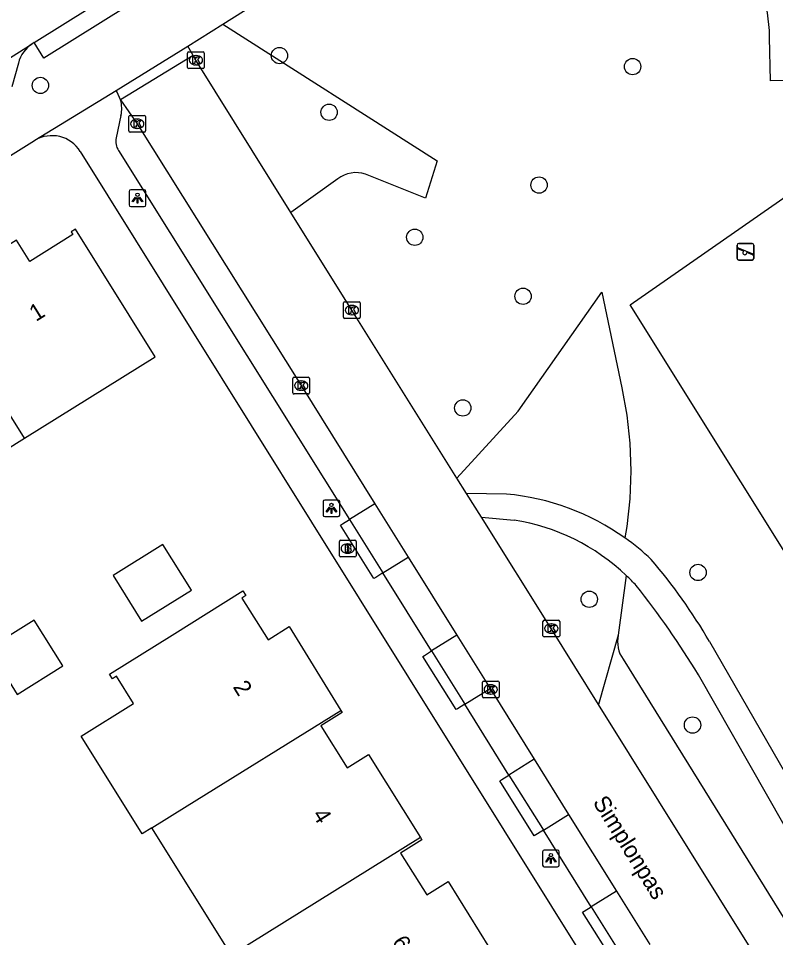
# Model space of a CAD drawing. Extents: x 158838 to 160074, y 386376 to 387776.
# Drawn here: x 159109.8 to 159155.2, y 387026.3 to 387081.4 of the extents above; entities that cross this region are included whole.
import ezdxf

# ---------------------------------------------------------------- set-up
doc = ezdxf.new("R2010")
doc.units = 0
for name, color, linetype in [('IMGEO_Boom', 7, 'Continuous'), ('IMGEO_Brandkraan', 7, 'Continuous'), ('IMGEO_Groenvoorziening', 7, 'Continuous'), ('IMGEO_Kolk', 7, 'Continuous'), ('IMGEO_Lichtpunt', 7, 'Continuous'), ('IMGEO_Muur', 7, 'Continuous'), ('IMGEO_Openbare_ruimte_label', 7, 'Continuous'), ('IMGEO_Pand', 7, 'Continuous'), ('IMGEO_Pand_nummerreeks', 7, 'Continuous'), ('IMGEO_Rijbaan_lokaal_open', 7, 'Continuous'), ('IMGEO_Speelvoorziening', 7, 'Continuous'), ('IMGEO_Voetpad_halfverhard', 7, 'Continuous'), ('IMGEO_Voetpad_open', 7, 'Continuous')]:
    doc.layers.add(name, color=color, linetype=linetype)

msp = doc.modelspace()

# ---------------------------------------------------------------- linework, layer by layer
at = {"layer": 'IMGEO_Boom'}
for centre in [(159125.412, 387079.149), (159146.581, 387078.488), (159111.083, 387077.358), (159128.389, 387075.753), (159140.974, 387071.393), (159133.524, 387068.262), (159140.012, 387064.726), (159136.402, 387058.036), (159150.502, 387048.181), (159143.982, 387046.575), (159150.172, 387039.039)]:
    msp.add_circle(centre, 0.489, dxfattribs=at)
at = {"layer": 'IMGEO_Brandkraan'}
for p, q in [((159129.004, 387049.186), (159129.004, 387050.038)), ((159129.079, 387050.112), (159129.931, 387050.112)), ((159129.492, 387049.892), (159129.517, 387049.892)), ((159130.005, 387050.038), (159130.005, 387049.186)), ((159129.515, 387049.332), (159129.49, 387049.332)), ((159129.931, 387049.112), (159129.079, 387049.112))]:
    msp.add_line(p, q, dxfattribs=at)
for points in [[(159129.004, 387049.186), (159129.004, 387050.038)], [(159129.079, 387050.112), (159129.931, 387050.112)], [(159130.005, 387050.038), (159130.005, 387049.186)], [(159129.352, 387049.812), (159129.352, 387049.412), (159129.565, 387049.412)], [(159129.583, 387049.812), (159129.352, 387049.812)], [(159129.531, 387049.731), (159129.477, 387049.731), (159129.477, 387049.655)], [(159129.477, 387049.655), (159129.53, 387049.655)], [(159129.539, 387049.579), (159129.477, 387049.579), (159129.477, 387049.498)], [(159129.477, 387049.498), (159129.539, 387049.498)], [(159129.931, 387049.112), (159129.079, 387049.112)]]:
    msp.add_lwpolyline(points, dxfattribs=at)
for centre, radius, start, end in [((159129.081, 387050.036), 0.0765, 91.552, 178.448), ((159129.081, 387050.036), 0.0765, 91.552, 178.448), ((159129.929, 387050.036), 0.0765, 1.552, 88.448), ((159129.929, 387050.036), 0.0765, 1.552, 88.448), ((159129.532, 387049.693), 0.0379, 267.8285, 90.9355), ((159129.54, 387049.538), 0.0404, 269.8759, 90.5077), ((159129.571, 387049.663), 0.251, 268.6676, 293.5347), ((159129.587, 387049.667), 0.145, 59.4692, 91.5367), ((159129.612, 387049.714), 0.0922, 285.5137, 58.1501), ((159129.617, 387049.522), 0.105, 301.3115, 78.989), ((159129.081, 387049.188), 0.0765, 181.552, 268.448), ((159129.081, 387049.188), 0.0765, 181.552, 268.448), ((159129.929, 387049.188), 0.0765, 271.552, 358.448), ((159129.929, 387049.188), 0.0765, 271.552, 358.448)]:
    msp.add_arc(centre, radius, start, end, dxfattribs=at)
for centre, major_axis, ratio, start_param, end_param in [((159129.491, 387049.612), (-0.387, 0.002), 0.722429, 4.712389, 7.853982), ((159129.516, 387049.612), (-0.39, 0.002), 0.717154, 1.570796, 4.712389)]:
    msp.add_ellipse(centre, major_axis=major_axis, ratio=ratio, start_param=start_param, end_param=end_param, dxfattribs=at)
at = {"layer": 'IMGEO_Groenvoorziening'}
for points in [[(159156.656, 387089.592), (159156.492, 387077.665), (159154.841, 387077.644), (159154.788, 387080.232), (159154.777, 387080.645), (159154.665, 387081.712), (159154.435, 387082.76), (159154.09, 387083.777), (159153.633, 387084.748), (159153.071, 387085.662), (159152.41, 387086.508), (159141.336, 387093.187)], [(159122.014, 387081.038), (159134.861, 387072.838), (159134.173, 387070.612), (159130.575, 387072.05)], [(159158.739, 387072.783), (159178.64, 387040.984), (159166.329, 387032.414), (159146.428, 387064.213), (159158.739, 387072.783)], [(159128.911, 387071.76), (159126.097, 387069.747)], [(159136.054, 387053.836), (159139.723, 387057.851), (159144.742, 387064.973), (159145.94, 387059.243), (159146.237, 387057.598), (159146.415, 387055.935), (159146.474, 387054.265), (159146.412, 387052.594), (159146.231, 387050.932), (159146.122, 387050.251)], [(159146.204, 387048.002), (159145.724, 387044.428)], [(159145.724, 387044.428), (159144.539, 387040.277)], [(159146.011, 387042.982), (159178.034, 386991.406)]]:
    msp.add_lwpolyline(points, dxfattribs=at)
for centre, radius, start, end in [((159130.019, 387070.32), 1.817, 72.1969, 127.5754), ((159147.494, 387044.028), 1.815, 167.2666, 215.1855)]:
    msp.add_arc(centre, radius, start, end, dxfattribs=at)
at = {"layer": 'IMGEO_Kolk'}
for p, q in [((159119.902, 387078.442), (159119.902, 387079.294)), ((159119.977, 387079.368), (159120.829, 387079.368)), ((159120.39, 387079.148), (159120.415, 387079.148)), ((159120.903, 387079.294), (159120.903, 387078.442)), ((159120.413, 387078.588), (159120.388, 387078.588)), ((159120.829, 387078.368), (159119.977, 387078.368)), ((159116.384, 387074.639), (159116.384, 387075.491)), ((159116.459, 387075.565), (159117.311, 387075.565)), ((159116.872, 387075.345), (159116.897, 387075.345)), ((159117.385, 387075.491), (159117.385, 387074.639)), ((159116.895, 387074.785), (159116.87, 387074.785)), ((159117.311, 387074.565), (159116.459, 387074.565)), ((159129.253, 387063.476), (159129.253, 387064.328)), ((159129.328, 387064.402), (159130.18, 387064.402)), ((159129.741, 387064.182), (159129.766, 387064.182)), ((159130.254, 387064.328), (159130.254, 387063.476)), ((159129.764, 387063.622), (159129.739, 387063.622)), ((159130.18, 387063.402), (159129.328, 387063.402)), ((159126.214, 387058.948), (159126.214, 387059.8)), ((159126.289, 387059.874), (159127.141, 387059.874)), ((159127.215, 387059.8), (159127.215, 387058.948)), ((159126.702, 387059.654), (159126.727, 387059.654)), ((159127.141, 387058.874), (159126.289, 387058.874)), ((159126.725, 387059.094), (159126.7, 387059.094)), ((159141.208, 387044.392), (159141.208, 387045.244)), ((159141.283, 387045.318), (159142.135, 387045.318)), ((159141.696, 387045.098), (159141.721, 387045.098)), ((159142.209, 387045.244), (159142.209, 387044.392)), ((159142.135, 387044.318), (159141.283, 387044.318)), ((159141.719, 387044.538), (159141.694, 387044.538)), ((159137.576, 387040.752), (159137.576, 387041.604)), ((159137.651, 387041.678), (159138.503, 387041.678)), ((159138.577, 387041.604), (159138.577, 387040.752)), ((159138.064, 387041.458), (159138.089, 387041.458)), ((159138.503, 387040.678), (159137.651, 387040.678)), ((159138.087, 387040.898), (159138.062, 387040.898))]:
    msp.add_line(p, q, dxfattribs=at)
for points in [[(159119.902, 387078.442), (159119.902, 387079.294)], [(159119.977, 387079.368), (159120.829, 387079.368)], [(159120.223, 387079.068), (159120.346, 387079.068), (159120.346, 387078.917), (159120.476, 387079.068), (159120.64, 387079.068), (159120.494, 387078.917), (159120.647, 387078.668), (159120.495, 387078.668), (159120.41, 387078.832), (159120.346, 387078.765), (159120.346, 387078.668), (159120.223, 387078.668), (159120.223, 387079.068)], [(159120.903, 387079.294), (159120.903, 387078.442)], [(159120.829, 387078.368), (159119.977, 387078.368)], [(159116.384, 387074.639), (159116.384, 387075.491)], [(159116.459, 387075.565), (159117.311, 387075.565)], [(159116.705, 387075.265), (159116.828, 387075.265), (159116.828, 387075.114), (159116.958, 387075.265), (159117.122, 387075.265), (159116.976, 387075.114), (159117.129, 387074.865), (159116.977, 387074.865), (159116.892, 387075.029), (159116.828, 387074.962), (159116.828, 387074.865), (159116.705, 387074.865), (159116.705, 387075.265)], [(159117.385, 387075.491), (159117.385, 387074.639)], [(159117.311, 387074.565), (159116.459, 387074.565)], [(159129.253, 387063.476), (159129.253, 387064.328)], [(159129.328, 387064.402), (159130.18, 387064.402)], [(159130.254, 387064.328), (159130.254, 387063.476)], [(159129.574, 387064.102), (159129.697, 387064.102), (159129.697, 387063.951), (159129.827, 387064.102), (159129.991, 387064.102), (159129.845, 387063.951), (159129.998, 387063.702), (159129.846, 387063.702), (159129.761, 387063.866), (159129.697, 387063.799), (159129.697, 387063.702), (159129.574, 387063.702), (159129.574, 387064.102)], [(159130.18, 387063.402), (159129.328, 387063.402)], [(159126.214, 387058.948), (159126.214, 387059.8)], [(159126.289, 387059.874), (159127.141, 387059.874)], [(159127.215, 387059.8), (159127.215, 387058.948)], [(159126.535, 387059.574), (159126.658, 387059.574), (159126.658, 387059.423), (159126.788, 387059.574), (159126.952, 387059.574), (159126.806, 387059.423), (159126.959, 387059.174), (159126.807, 387059.174), (159126.722, 387059.338), (159126.658, 387059.271), (159126.658, 387059.174), (159126.535, 387059.174), (159126.535, 387059.574)], [(159127.141, 387058.874), (159126.289, 387058.874)], [(159141.208, 387044.392), (159141.208, 387045.244)], [(159141.283, 387045.318), (159142.135, 387045.318)], [(159141.529, 387045.018), (159141.652, 387045.018), (159141.652, 387044.867), (159141.782, 387045.018), (159141.946, 387045.018), (159141.8, 387044.867), (159141.953, 387044.618), (159141.801, 387044.618), (159141.716, 387044.782), (159141.652, 387044.715), (159141.652, 387044.618), (159141.529, 387044.618), (159141.529, 387045.018)], [(159142.209, 387045.244), (159142.209, 387044.392)], [(159142.135, 387044.318), (159141.283, 387044.318)], [(159137.576, 387040.752), (159137.576, 387041.604)], [(159137.651, 387041.678), (159138.503, 387041.678)], [(159138.577, 387041.604), (159138.577, 387040.752)], [(159137.897, 387041.378), (159138.02, 387041.378), (159138.02, 387041.227), (159138.15, 387041.378), (159138.314, 387041.378), (159138.168, 387041.227), (159138.321, 387040.978), (159138.169, 387040.978), (159138.084, 387041.142), (159138.02, 387041.075), (159138.02, 387040.978), (159137.897, 387040.978), (159137.897, 387041.378)], [(159138.503, 387040.678), (159137.651, 387040.678)]]:
    msp.add_lwpolyline(points, dxfattribs=at)
for centre, start, end in [((159119.979, 387079.292), 91.552, 178.448), ((159119.979, 387079.292), 91.552, 178.448), ((159120.827, 387079.292), 1.552, 88.448), ((159120.827, 387079.292), 1.552, 88.448), ((159119.979, 387078.444), 181.552, 268.448), ((159119.979, 387078.444), 181.552, 268.448), ((159120.827, 387078.444), 271.552, 358.448), ((159120.827, 387078.444), 271.552, 358.448), ((159116.461, 387075.489), 91.552, 178.448), ((159116.461, 387075.489), 91.552, 178.448), ((159117.309, 387075.489), 1.552, 88.448), ((159117.309, 387075.489), 1.552, 88.448), ((159116.461, 387074.641), 181.552, 268.448), ((159116.461, 387074.641), 181.552, 268.448), ((159117.309, 387074.641), 271.552, 358.448), ((159117.309, 387074.641), 271.552, 358.448), ((159129.33, 387064.326), 91.552, 178.448), ((159129.33, 387064.326), 91.552, 178.448), ((159130.178, 387064.326), 1.552, 88.448), ((159130.178, 387064.326), 1.552, 88.448), ((159129.33, 387063.478), 181.552, 268.448), ((159129.33, 387063.478), 181.552, 268.448), ((159130.178, 387063.478), 271.552, 358.448), ((159130.178, 387063.478), 271.552, 358.448), ((159126.291, 387059.798), 91.552, 178.448), ((159126.291, 387059.798), 91.552, 178.448), ((159127.139, 387059.798), 1.552, 88.448), ((159127.139, 387059.798), 1.552, 88.448), ((159126.291, 387058.95), 181.552, 268.448), ((159126.291, 387058.95), 181.552, 268.448), ((159127.139, 387058.95), 271.552, 358.448), ((159127.139, 387058.95), 271.552, 358.448), ((159141.285, 387045.242), 91.552, 178.448), ((159141.285, 387045.242), 91.552, 178.448), ((159142.133, 387045.242), 1.552, 88.448), ((159142.133, 387045.242), 1.552, 88.448), ((159141.285, 387044.394), 181.552, 268.448), ((159141.285, 387044.394), 181.552, 268.448), ((159142.133, 387044.394), 271.552, 358.448), ((159142.133, 387044.394), 271.552, 358.448), ((159137.653, 387041.602), 91.552, 178.448), ((159137.653, 387041.602), 91.552, 178.448), ((159138.501, 387041.602), 1.552, 88.448), ((159138.501, 387041.602), 1.552, 88.448), ((159137.653, 387040.754), 181.552, 268.448), ((159137.653, 387040.754), 181.552, 268.448), ((159138.501, 387040.754), 271.552, 358.448), ((159138.501, 387040.754), 271.552, 358.448)]:
    msp.add_arc(centre, 0.0765, start, end, dxfattribs=at)
for centre, major_axis, ratio, start_param, end_param in [((159120.389, 387078.868), (-0.387, 0.002), 0.722429, 4.712389, 7.853982), ((159120.414, 387078.868), (-0.39, 0.002), 0.717154, 1.570796, 4.712389), ((159116.871, 387075.065), (-0.387, 0.002), 0.722429, 4.712389, 7.853982), ((159116.896, 387075.065), (-0.39, 0.002), 0.717154, 1.570796, 4.712389), ((159129.74, 387063.902), (-0.387, 0.002), 0.722429, 4.712389, 7.853982), ((159129.765, 387063.902), (-0.39, 0.002), 0.717154, 1.570796, 4.712389), ((159126.701, 387059.374), (-0.387, 0.002), 0.722429, 4.712389, 7.853982), ((159126.726, 387059.374), (-0.39, 0.002), 0.717154, 1.570796, 4.712389), ((159141.695, 387044.818), (-0.387, 0.002), 0.722429, 4.712389, 7.853982), ((159141.72, 387044.818), (-0.39, 0.002), 0.717154, 1.570796, 4.712389), ((159138.063, 387041.178), (-0.387, 0.002), 0.722429, 4.712389, 7.853982), ((159138.088, 387041.178), (-0.39, 0.002), 0.717154, 1.570796, 4.712389)]:
    msp.add_ellipse(centre, major_axis=major_axis, ratio=ratio, start_param=start_param, end_param=end_param, dxfattribs=at)
at = {"layer": 'IMGEO_Lichtpunt'}
for p, q in [((159116.403, 387071.01), (159116.403, 387070.203)), ((159116.403, 387071.01), (159116.403, 387070.203)), ((159117.305, 387071.105), (159116.497, 387071.105)), ((159117.305, 387071.105), (159116.497, 387071.105)), ((159117.399, 387070.203), (159117.399, 387071.01)), ((159117.399, 387070.203), (159117.399, 387071.01)), ((159116.497, 387070.109), (159117.305, 387070.109)), ((159116.497, 387070.109), (159117.305, 387070.109)), ((159128.03, 387052.428), (159128.03, 387051.621)), ((159128.03, 387052.428), (159128.03, 387051.621)), ((159128.932, 387052.523), (159128.124, 387052.523)), ((159128.932, 387052.523), (159128.124, 387052.523)), ((159129.026, 387051.621), (159129.026, 387052.428)), ((159129.026, 387051.621), (159129.026, 387052.428)), ((159128.124, 387051.527), (159128.932, 387051.527)), ((159128.124, 387051.527), (159128.932, 387051.527)), ((159141.183, 387031.454), (159141.183, 387030.647)), ((159141.183, 387031.454), (159141.183, 387030.647)), ((159142.085, 387031.549), (159141.277, 387031.549)), ((159142.085, 387031.549), (159141.277, 387031.549)), ((159142.179, 387030.647), (159142.179, 387031.454)), ((159142.179, 387030.647), (159142.179, 387031.454)), ((159141.277, 387030.553), (159142.085, 387030.553)), ((159141.277, 387030.553), (159142.085, 387030.553))]:
    msp.add_line(p, q, dxfattribs=at)
for points in [[(159116.777, 387070.674), (159116.816, 387070.646), (159116.628, 387070.384), (159116.59, 387070.411), (159116.777, 387070.674)], [(159116.879, 387070.626), (159116.926, 387070.626), (159116.926, 387070.304), (159116.879, 387070.304), (159116.879, 387070.626)], [(159116.989, 387070.646), (159117.027, 387070.673), (159117.214, 387070.411), (159117.175, 387070.383), (159116.989, 387070.646)], [(159128.404, 387052.092), (159128.443, 387052.064), (159128.255, 387051.802), (159128.217, 387051.829), (159128.404, 387052.092)], [(159128.506, 387052.044), (159128.553, 387052.044), (159128.553, 387051.722), (159128.506, 387051.722), (159128.506, 387052.044)], [(159128.616, 387052.064), (159128.654, 387052.091), (159128.841, 387051.829), (159128.802, 387051.801), (159128.616, 387052.064)], [(159141.557, 387031.118), (159141.596, 387031.09), (159141.408, 387030.828), (159141.37, 387030.855), (159141.557, 387031.118)], [(159141.769, 387031.09), (159141.807, 387031.117), (159141.994, 387030.855), (159141.955, 387030.827), (159141.769, 387031.09)], [(159141.659, 387031.07), (159141.706, 387031.07), (159141.706, 387030.748), (159141.659, 387030.748), (159141.659, 387031.07)]]:
    msp.add_lwpolyline(points, dxfattribs=at)
for centre in [(159116.902, 387070.808), (159128.529, 387052.226), (159141.682, 387031.252)]:
    msp.add_circle(centre, 0.0994, dxfattribs=at)
for centre, start, end in [((159116.497, 387071.01), 90, 180), ((159116.497, 387071.01), 90, 180), ((159117.305, 387071.01), 0, 90), ((159117.305, 387071.01), 0, 90), ((159116.497, 387070.203), 180, 270), ((159116.497, 387070.203), 180, 270), ((159117.305, 387070.203), 270, 0), ((159117.305, 387070.203), 270, 360), ((159128.124, 387052.428), 90, 180), ((159128.124, 387052.428), 90, 180), ((159128.932, 387052.428), 0, 90), ((159128.932, 387052.428), 0, 90), ((159128.124, 387051.621), 180, 270), ((159128.124, 387051.621), 180, 270), ((159128.932, 387051.621), 270, 0), ((159128.932, 387051.621), 270, 360), ((159141.277, 387031.454), 90, 180), ((159141.277, 387031.454), 90, 180), ((159142.085, 387031.454), 0, 90), ((159142.085, 387031.454), 0, 90), ((159141.277, 387030.647), 180, 270), ((159141.277, 387030.647), 180, 270), ((159142.085, 387030.647), 270, 0), ((159142.085, 387030.647), 270, 360)]:
    msp.add_arc(centre, 0.0946, start, end, dxfattribs=at)
at = {"layer": 'IMGEO_Muur'}
msp.add_lwpolyline([(159120.104, 387062.784), (159127.342, 387051.2)], dxfattribs=at)
at = {"layer": 'IMGEO_Pand'}
for points in [[(159110.127, 387056.22), (159117.951, 387061.11), (159113.194, 387068.752), (159112.923, 387068.583), (159113.018, 387068.431), (159110.438, 387066.82), (159109.646, 387068.089), (159104.655, 387064.968)], [(159110.127, 387056.22), (159104.655, 387064.968)], [(159102.49, 387051.447), (159110.127, 387056.22)], [(159115.439, 387047.998), (159117.148, 387045.262), (159120.135, 387047.127), (159118.427, 387049.864), (159115.439, 387047.998)], [(159117.771, 387032.888), (159117.177, 387032.519), (159113.521, 387038.376), (159116.658, 387040.335), (159115.641, 387041.964), (159115.395, 387041.811), (159115.226, 387042.082), (159118.985, 387044.429), (159123.226, 387047.077), (159123.397, 387046.805), (159123.151, 387046.65), (159124.729, 387044.145), (159126.003, 387044.947), (159129.085, 387039.923)], [(159107.976, 387043.627), (159109.692, 387040.879), (159112.424, 387042.585), (159110.708, 387045.333), (159107.976, 387043.627)], [(159117.771, 387032.888), (159119.886, 387034.203), (159129.085, 387039.923)], [(159129.085, 387039.923), (159129.169, 387039.787), (159127.9, 387038.991), (159129.471, 387036.486), (159130.74, 387037.282), (159133.86, 387032.308)], [(159122.54, 387025.25), (159117.771, 387032.888)], [(159133.86, 387032.308), (159124.653, 387026.567), (159122.54, 387025.25)], [(159133.86, 387032.308), (159133.945, 387032.172), (159132.676, 387031.376), (159134.247, 387028.871), (159135.516, 387029.667), (159138.623, 387024.672)]]:
    msp.add_lwpolyline(points, dxfattribs=at)
at = {"layer": 'IMGEO_Rijbaan_lokaal_open'}
for points in [[(159110.704, 387079.928), (159119.193, 387085.238)], [(159064.66, 387051.128), (159066.593, 387052.325), (159084.528, 387063.55), (159103.151, 387075.188), (159110.593, 387079.859)], [(159110.704, 387079.928), (159110.593, 387079.859)], [(159120.238, 387079.152), (159115.888, 387076.492)], [(159126.097, 387069.747), (159120.398, 387078.868), (159120.238, 387079.152)], [(159115.888, 387076.492), (159116.882, 387075.066), (159126.712, 387059.374), (159131.128, 387052.302)], [(159136.054, 387053.836), (159129.749, 387063.902), (159126.097, 387069.747)], [(159136.626, 387052.922), (159136.054, 387053.836)], [(159137.526, 387051.487), (159136.626, 387052.922)], [(159131.128, 387052.302), (159133.126, 387049.103)], [(159144.539, 387040.277), (159141.704, 387044.817), (159137.526, 387051.487)], [(159133.126, 387049.103), (159136.047, 387044.424)], [(159136.047, 387044.424), (159138.038, 387041.236)], [(159138.038, 387041.236), (159138.074, 387041.179), (159140.687, 387036.989)], [(159176.816, 386988.577), (159174.277, 386992.643), (159169.676, 387000), (159163.428, 387009.991), (159153.626, 387025.725), (159144.539, 387040.277)], [(159140.687, 387036.989), (159142.744, 387033.69)], [(159142.744, 387033.69), (159145.61, 387029.095)], [(159145.61, 387029.095), (159147.608, 387025.891)]]:
    msp.add_lwpolyline(points, dxfattribs=at)
at = {"layer": 'IMGEO_Speelvoorziening'}
for p, q in [((159152.849, 387066.998), (159152.849, 387067.798)), ((159152.849, 387067.798), (159152.849, 387066.998)), ((159153.232, 387067.426), (159152.893, 387067.563)), ((159152.918, 387067.623), (159153.794, 387067.27)), ((159152.949, 387067.898), (159153.739, 387067.898)), ((159153.739, 387067.898), (159152.949, 387067.898)), ((159153.839, 387067.798), (159153.839, 387066.998)), ((159153.839, 387066.998), (159153.839, 387067.798)), ((159153.739, 387066.898), (159152.949, 387066.898)), ((159152.949, 387066.898), (159153.739, 387066.898)), ((159153.77, 387067.21), (159153.43, 387067.347))]:
    msp.add_line(p, q, dxfattribs=at)
for centre, radius, start, end in [((159152.949, 387067.798), 0.1, 90, 180), ((159152.949, 387067.798), 0.1, 90, 180), ((159152.906, 387067.593), 0.0327, 68.078, 248.078), ((159153.739, 387067.798), 0.1, 0, 90), ((159153.739, 387067.798), 0.1, 360, 90), ((159152.949, 387066.998), 0.1, 180, 270), ((159152.949, 387066.998), 0.1, 180, 270), ((159153.311, 387067.336), 0.12, 130.9928, 5.1632), ((159153.739, 387066.998), 0.1, 270, 0), ((159153.739, 387066.998), 0.1, 270, 0), ((159153.782, 387067.24), 0.0327, 248.078, 68.078)]:
    msp.add_arc(centre, radius, start, end, dxfattribs=at)
at = {"layer": 'IMGEO_Voetpad_halfverhard'}
for points in [[(159139.018, 387052.882), (159136.626, 387052.922)], [(159137.526, 387051.487), (159139.474, 387051.325)], [(159151.191, 387044.049), (159163.807, 387022.152)], [(159178.96, 386991.921), (159174.259, 386999.753), (159172.04, 387003.598), (159170.055, 387007.101), (159163.903, 387018.599), (159150.526, 387042.058)]]:
    msp.add_lwpolyline(points, dxfattribs=at)
for centre, radius, start, end in [((159137.649, 387038.279), 14.667, 54.7111, 84.6442), ((159137.467, 387038.783), 12.701, 46.5363, 80.9071), ((159137.738, 387038.382), 14.531, 46.7467, 54.7618), ((159121.003, 387026.286), 35.027, 30.4723, 40.3535), ((159138.187, 387039.492), 11.691, 42.5299, 46.71), ((159104.306, 387013.783), 54.183, 31.4564, 38.3416)]:
    msp.add_arc(centre, radius, start, end, dxfattribs=at)
at = {"layer": 'IMGEO_Voetpad_open'}
for points in [[(159122.014, 387081.038), (159141.336, 387093.187)], [(159119.193, 387085.238), (159119.776, 387084.305), (159111.287, 387078.995), (159110.704, 387079.928)], [(159119.918, 387079.72), (159122.014, 387081.038)], [(159115.626, 387077.064), (159119.918, 387079.72)], [(159120.238, 387079.152), (159119.918, 387079.72)], [(159109.761, 387078.703), (159109.364, 387077.279)], [(159110.736, 387074.06), (159110.756, 387074.075), (159115.626, 387077.064)], [(159115.888, 387076.492), (159115.691, 387076.96), (159115.626, 387077.064)], [(159115.912, 387075.556), (159115.623, 387074.217)], [(159063.193, 387044.393), (159110.736, 387074.06)], [(159113.472, 387073.398), (159120.104, 387062.784), (159127.342, 387051.2), (159176.412, 386972.666)], [(159115.765, 387073.461), (159129.615, 387051.357)], [(159131.128, 387052.302), (159129.615, 387051.357)], [(159131.605, 387048.153), (159131.181, 387047.89), (159131.061, 387047.815), (159129.062, 387051.014), (159129.191, 387051.094), (159129.615, 387051.357)], [(159129.615, 387051.357), (159131.605, 387048.153)], [(159131.605, 387048.153), (159133.126, 387049.103)], [(159134.532, 387043.478), (159131.605, 387048.153)], [(159136.047, 387044.424), (159134.532, 387043.478)], [(159136.518, 387040.287), (159136.094, 387040.023), (159136.007, 387039.968), (159134.015, 387043.156), (159134.108, 387043.214), (159134.532, 387043.478)], [(159134.532, 387043.478), (159136.518, 387040.287)], [(159136.518, 387040.287), (159138.038, 387041.236)], [(159139.168, 387036.042), (159136.518, 387040.287)], [(159140.687, 387036.989), (159139.168, 387036.042)], [(159141.232, 387032.745), (159140.687, 387032.405), (159138.626, 387035.703), (159138.745, 387035.777), (159139.168, 387036.042)], [(159139.168, 387036.042), (159141.172, 387032.84), (159141.232, 387032.745)], [(159141.232, 387032.745), (159142.744, 387033.69)], [(159144.098, 387028.152), (159141.232, 387032.745)], [(159145.61, 387029.095), (159144.098, 387028.152)], [(159146.094, 387024.947), (159145.588, 387024.632), (159143.587, 387027.834), (159143.674, 387027.888), (159144.098, 387028.152)], [(159144.098, 387028.152), (159146.094, 387024.947)]]:
    msp.add_lwpolyline(points, dxfattribs=at)
for centre, radius, start, end in [((159111.748, 387078.15), 2.063, 124.0604, 164.4528), ((159114.007, 387075.975), 1.951, 347.5834, 15.3542), ((159111.772, 387072.359), 1.992, 31.4434, 121.353), ((159116.57, 387074.004), 0.971, 167.3009, 213.975)]:
    msp.add_arc(centre, radius, start, end, dxfattribs=at)

# ---------------------------------------------------------------- texts
at = {"layer": 'IMGEO_Openbare_ruimte_label'}
msp.add_text('Simplonpas', height=1, rotation=301.9568, dxfattribs=at).set_placement((159144.163, 387034.419))
at = {"layer": 'IMGEO_Pand_nummerreeks'}
for s, rotation, p in [('1', 32.0045, (159110.815, 387063.186)), ('2', 301.7989, (159122.592, 387041.328)), ('4', 301.9995, (159127.356, 387033.672)), ('6', 301.9995, (159132.124, 387026.042))]:
    msp.add_text(s, height=1, rotation=rotation, dxfattribs=at).set_placement(p)

doc.saveas('drawing.dxf')
